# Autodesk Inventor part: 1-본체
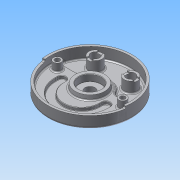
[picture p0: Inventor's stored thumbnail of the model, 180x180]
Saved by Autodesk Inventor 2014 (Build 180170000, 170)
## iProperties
Created: 2015-06
Part Number: 1-본체
Material: 알루미늄 6061
Document SubType Name: Modeling
Designer: Administrator
Density: 2.71 g/cm^3
Appearance: 알루미늄 - 평지
Mass: 1071 g
Surface Area: 1034.49 cm^2
Volume: 395.202 cm^3
Author: Administrator
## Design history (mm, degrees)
sketch "스케치1"
  geometry: C1 r 95 at (0, 0); 1 further point
  constraints: 1 centre point, 1 coincident
  dimensions: "d0" = 190 diameter of C1
extrude "돌출1" new body sketch "스케치1" distance "d1" = 32; taper "d2" = 0 deg
feature "쉘1" dims "d3" = 7, "d4" = 5
sketch "스케치2"
  geometry: L1 (38.833, 16)-(75.657, 16); L2 (-38.833, 16)-(-75.657, 16); A1 r 90 centre (0, 0) between (88.566, 16) and (-88.566, 16) reference; A2 r 42 centre (0, 0) between (38.833, 16) and (-38.833, 16); A3 r 90 centre (0, 0) between (85.114, 29.25) and (-85.114, 29.25); A4 r 10 centre (-75.657, 26) between (-85.114, 29.25) and (-75.657, 16); A5 r 10 centre (75.657, 26) between (75.657, 16) and (85.114, 29.25)
  constraints: 12 point on circle, 4 centre point, 4 end point, 4 tangent, 2 coincident, 2 collinear, 2 point on line, 1 equal radius, 1 horizontal
  dimensions: "d5" = 84 diameter of A2; "d6" = 16 distance from line of A1.centre L1; "d7" = 10 radius of A4
extrude "돌출2" join sketch "스케치2" distance "d8" = 7; taper "d9" = 0 deg
sketch "스케치3"
  geometry: C1 r 35 at (0, 0); A1 r 90 centre (0, 0) between (-85.114, 29.25) and (85.114, 29.25) reference
  constraints: 1 centre point, 1 coincident
  dimensions: "d10" = 70 diameter of C1
extrude "돌출3" join sketch "스케치3" distance "d11" = 10; taper "d12" = -10 deg
sketch "스케치4"
  geometry: C1 r 95 at (0, 0) reference; C2 r 26 at (0, 0)
  constraints: 1 centre point, 1 coincident
  dimensions: "d13" = 52 diameter of C2
extrude "돌출4" join sketch "스케치4" distance "d14" = 12; taper "d15" = -15 deg
hole "구멍1" diameter "d18" = 23; stored, may be unused: countersink angle "d22" = 90 deg, drill point angle "d24" = 118 deg; dims "d16" = 10, "d17" = 10, "d19" = 6, "d20" = 50, "d21" = 15, "d23" = 8
sketch "스케치5"
  geometry: L1 (-38.833, 16)-(-75.657, 16) reference; L2 (-59, -19)-(-59, -14); L3 (-41, -19)-(-41, -14); L4 (41, -19)-(41, -14); L5 (59, -19)-(59, -14); C1 r 35 at (0, 0) reference; A1 r 41 centre (0, -19) between (-41, -19) and (41, -19); A2 r 59 centre (0, -19) between (-59, -19) and (59, -19); A3 r 9 centre (-50, -14) between (-41, -14) and (-59, -14); A4 r 9 centre (50, -14) between (59, -14) and (41, -14); 1 further point
  constraints: 8 end point, 8 point on circle, 8 tangent, 6 parallel, 4 centre point, 2 coincident, 1 perpendicular, 1 vertical alignment
  dimensions: "d25" = 19 distance of A2.centre C1.centre; "d28" = 41 radius of A1; "d29" = 59 radius of A2; "d30" = 5 distance of L2.start L2.end
extrude "돌출5" cut sketch "스케치5" distance "d31" = 7; taper "d32" = 0 deg
sketch "스케치6"
  geometry: L1 (0, 133)-(0, -133) reference; C1 r 15 at (-40, 52); C2 r 15 at (40, 52); A1 r 42 centre (0, 0) between (38.833, 16) and (-38.833, 16) reference
  constraints: 2 centre point, 1 equal radius, 1 horizontal alignment, 1 other
  dimensions: "d33" = 30 diameter of C1; "d34" = 52 vertical distance of A1.centre C2.centre; "d35" = 80 distance of C2.centre C1.centre
extrude "돌출6" join sketch "스케치6" distance "d36" = 25; taper "d37" = 0 deg
sketch "스케치7"
  geometry: L1 (6, -17.5)-(-6, -17.5); L2 (-6, -17.5)-(-6, 17.5); L3 (-6, 17.5)-(6, 17.5); L4 (6, 17.5)-(6, -17.5); L5 (6, -17.5)-(-6, 17.5); L6 (-6, -17.5)-(6, 17.5); L7 (97.5, -6)-(62.5, -6); L8 (62.5, -6)-(62.5, 6); L9 (62.5, 6)-(97.5, 6); L10 (97.5, 6)-(97.5, -6); L11 (97.5, -6)-(62.5, 6); L12 (62.5, -6)-(97.5, 6); C1 r 15 at (0, 0) reference; C2 r 15 at (80, 0) reference; 1 further point
  constraints: 24 end point, 4 midpoint, 4 parallel, 4 perpendicular, 2 horizontal
  dimensions: "d38" = 12 distance of L2.end L3.end; "d39" = 35 distance of L3.end L1.start
extrude "돌출7" cut sketch "스케치7" distance "d40" = 3; taper "d41" = 0 deg
sketch "스케치8"
  geometry: L1 (26.252, 58)-(53.748, 58) reference; A1 r 15 centre (-40, 52) between (-46, 65.748) and (-46, 38.252) reference; A2 r 15 centre (40, 52) between (53.748, 58) and (26.252, 58) reference; 3 further points
  constraints: 2 coincident
hole "구멍2" sketch "스케치8" at (-40, 52), (40, 52) diameter "d42" = 20; stored, may be unused: countersink angle "d46" = 90 deg, drill point angle "d48" = 118 deg; dims "d43" = 6, "d44" = 50, "d45" = 15, "d47" = 8
sketch "스케치9"
  geometry: L1 (0, 133)-(0, -133) reference; C1 r 35 at (0, 0) reference; C2 r 9 at (-74, 0); C3 r 9 at (74, 0)
  constraints: 2 centre point, 1 equal radius, 1 horizontal alignment, 1 other
  dimensions: "d49" = 18 diameter of C2; "d50" = 148 distance of C3.centre C2.centre
extrude "돌출8" join sketch "스케치9" distance "d51" = 18; taper "d52" = 0 deg
sketch "스케치10"
  geometry: C1 r 9 at (74, 0) reference; C2 r 9 at (-74, 0) reference; 2 further points
  constraints: 2 coincident
hole "구멍3" sketch "스케치10" at (-74, 0), (74, 0) diameter "d53" = 11; stored, may be unused: countersink angle "d57" = 90 deg, drill point angle "d59" = 118 deg; dims "d54" = 6, "d55" = 18, "d56" = 11, "d58" = 8
sketch "스케치11"
  geometry: L1 (0, 0)-(-89.124, -12.526); L2 (-133, 0)-(133, 0) reference; L3 (0, 0)-(89.124, -12.526); L4 (-89.124, -12.526)-(-94.075, -13.221); L5 (89.124, -12.526)-(94.075, -13.221); A1 r 90 centre (0, 0) between (-89.124, -12.526) and (89.124, -12.526) reference; A2 r 95 centre (0, 0) between (-94.075, -13.221) and (94.075, -13.221) reference; A3 r 95 centre (0, 0) between (-94.075, -13.221) and (94.075, -13.221); A4 r 90 centre (0, 0) between (-89.124, -12.526) and (89.124, -12.526)
  constraints: 8 end point, 8 point on circle, 2 centre point, 2 coincident, 2 collinear
  dimensions: "d60" = 8 deg angle of L1 L2; "d61" = 8 deg angle of L3 L2
extrude "돌출9" cut sketch "스케치11" distance "d62" = 5; taper "d63" = 0 deg
chamfer "모따기1" distance "d64" = 1; stored, may be unused: second distance "d65" = 2, angle "d66" = 45 deg
fillet "모깎기1" dims "d67" = 0.3
fillet "모깎기2" dims "d68" = 5
fillet "모깎기3" dims "d69" = 1
fillet "모깎기4" dims "d70" = 3
fillet "모깎기5" dims "d71" = 3
fillet "모깎기8" dims "d74" = 3
fillet "모깎기9" dims "d75" = 3
sketch "스케치12"
  geometry: C1 r 28.302 at (0, 0) reference; C2 r 68 at (0, 0)
  constraints: 1 centre point, 1 coincident, 1 other
  dimensions: "d76" = 136 diameter of C2
feature "엠보싱1" sketch "스케치12" dims "d77" = 0.5, "d78" = 0
fillet "모깎기13" dims "d82" = 10
fillet "모깎기14" dims "d83" = 3
node "솔리드1"
node "투영된 루프1"
node "투영된 루프2"
other parameters: "d26" = 118, "d27" = 82
